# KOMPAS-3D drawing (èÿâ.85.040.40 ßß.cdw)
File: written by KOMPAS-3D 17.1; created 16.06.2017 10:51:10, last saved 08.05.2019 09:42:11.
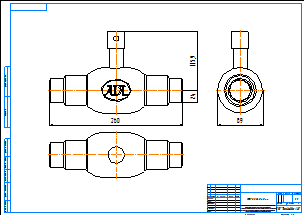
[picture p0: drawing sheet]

Sheet 1: A2, landscape

Title block, sheet 1: name: КШГ.85.040.40 сс; material: Внимание! Данный продукт является объектом авторского права ООО «Торговый Дом АДЛ». / Запрещается изменение, копирование, распространение / (в том числе путем копирования на другие сайты и ресурсы в Интернете) / или любое иное использование информации и объектов без предварительного / согласия правообладателя (ООО «Торговый Дом АДЛ»).; scale: 1:1; sheets: 1; organisation: ООО "Торговый дом АДЛ"; sheet format: A2; stored path: C:\Users\tra\Desktop\2д чертежи\Шаровые краны БИВАЛ\КШ_Бивал_серия_82_85\KOMPAS 2D\КШГ.85.040.40 сс.cdw

Views: Спереди 1, Проекционный вид 2, Проекционный вид 3
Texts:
  Klimkovich
  ADL
Dimensions and other numbers on the sheet: 260; 115,9; 24; 89; 1:1; 1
